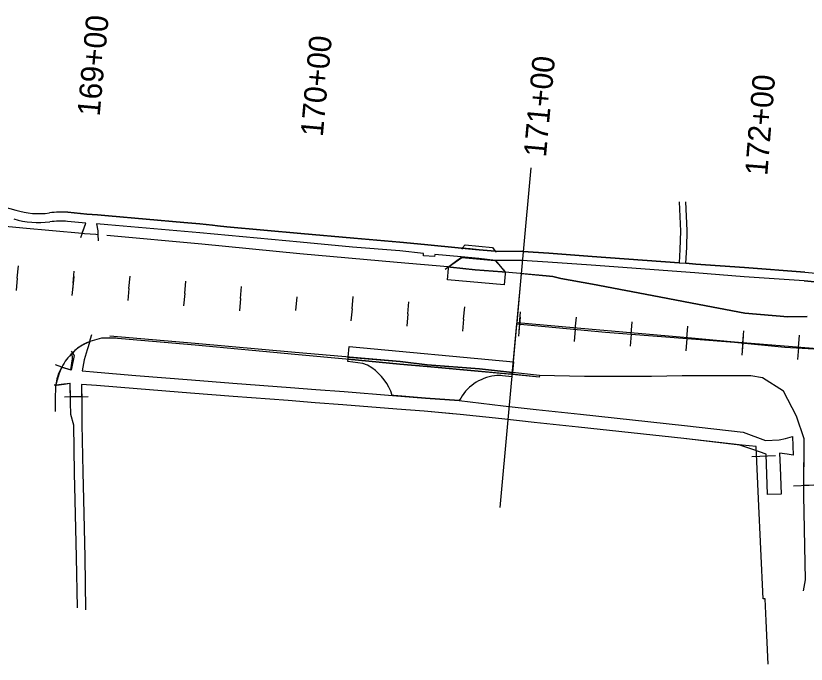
# Model space of a CAD drawing. Extents: x 20499880 to 20505309, y 7953507 to 7955507.
# Drawn here: x 20500587 to 20500939.7, y 7953820.8 to 7954110 of the extents above; entities that cross this region are included whole.
import ezdxf

# ---------------------------------------------------------------- set-up
doc = ezdxf.new("R2010")
doc.units = 0
for name, color, linetype in [('Alignment', 7, 'Continuous'), ('Curb', 7, 'Continuous'), ('Draft_0', 7, 'Continuous'), ('Entrance', 7, 'Continuous')]:
    doc.layers.add(name, color=color, linetype=linetype)

msp = doc.modelspace()

# ---------------------------------------------------------------- linework, layer by layer
at = {"layer": 'Alignment'}
for p, q in [((20500612.57, 7953990.69), (20500613.07, 7953996.12)), ((20500612.57, 7953990.69), (20500612.07, 7953985.25)), ((20500712.43, 7953984.62), (20500711.88, 7953978.53)), ((20500712.43, 7953984.62), (20500711.88, 7953978.53)), ((20500811.74, 7953972.46), (20500812.24, 7953977.9)), ((20500811.74, 7953972.46), (20500811.24, 7953967.02)), ((20500911.39, 7953964.08), (20500911.82, 7953969.52)), ((20500911.39, 7953964.08), (20500910.95, 7953958.64))]:
    msp.add_line(p, q, dxfattribs=at)
at = {"layer": 'Curb'}
for p, q in [((20500803.12, 7953890.74), (20500816.98, 7954042.24)), ((20500882.98, 7954026.94), (20500883.66, 7954013.96)), ((20500618.64, 7954021.56), (20500610.26, 7954022.39)), ((20500623.52, 7954021.15), (20500618.64, 7954021.56)), ((20500628.3, 7954020.71), (20500623.52, 7954021.15)), ((20500661.93, 7954017.8), (20500628.3, 7954020.71)), ((20500618.21, 7954017.54), (20500610.14, 7954018.27)), ((20500616.63, 7954013), (20500618.21, 7954017.54)), ((20500669.12, 7954017.16), (20500661.93, 7954017.8)), ((20500674.72, 7954016.63), (20500669.12, 7954017.16)), ((20500676.97, 7954016.28), (20500674.72, 7954016.63)), ((20500681.19, 7954015.83), (20500676.97, 7954016.28)), ((20500714.26, 7954012.88), (20500681.19, 7954015.83)), ((20500883.66, 7954013.96), (20500883.25, 7954005.81)), ((20500616.63, 7954013), (20500615.93, 7954010.98)), ((20500623.66, 7954012.45), (20500623.75, 7954009.64)), ((20500737.77, 7954010.78), (20500714.26, 7954012.88)), ((20500758.39, 7954009.06), (20500737.77, 7954010.78)), ((20500769.44, 7954007.93), (20500758.39, 7954009.06)), ((20500785.84, 7954006.38), (20500769.44, 7954007.93)), ((20500786.23, 7954006.36), (20500785.81, 7954005.88)), ((20500793.77, 7954005.61), (20500785.84, 7954006.38)), ((20500800.95, 7954005.06), (20500793.77, 7954005.61)), ((20500800.83, 7954005.1), (20500801.21, 7954004.6)), ((20500813.25, 7954004.92), (20500800.95, 7954005.06)), ((20500824.79, 7954004.16), (20500813.25, 7954004.92)), ((20500844.22, 7954002.69), (20500824.79, 7954004.16)), ((20500883.25, 7954005.81), (20500883, 7953999.85)), ((20500883, 7953999.85), (20500844.22, 7954002.69)), ((20500883, 7953999.85), (20500886, 7953999.67)), ((20500619.91, 7953964.38), (20500620.92, 7953967.89)), ((20500619.99, 7953964.72), (20500618.87, 7953964.16)), ((20500625.3, 7953966.21), (20500619.99, 7953964.72)), ((20500631.72, 7953966.19), (20500625.3, 7953966.21)), ((20500613.39, 7953960.67), (20500612.32, 7953959.54)), ((20500612.4, 7953959.57), (20500611.89, 7953960.45)), ((20500607.54, 7953953.34), (20500604.71, 7953954.25)), ((20500607.6, 7953953.31), (20500607.05, 7953952.29)), ((20500605.14, 7953946.48), (20500604.75, 7953945.1)), ((20500605.14, 7953945.29), (20500604.09, 7953945.17)), ((20500604.66, 7953944.09), (20500604.53, 7953939.56)), ((20500604.75, 7953945.1), (20500604.66, 7953944.09)), ((20500604.53, 7953939.56), (20500604.59, 7953936.8)), ((20500608.77, 7953940.02), (20500619.37, 7953940.18)), ((20500604.59, 7953936.8), (20500604.51, 7953933.47)), ((20500925.96, 7953913.79), (20500915.36, 7953913.31)), ((20500968.09, 7953901.45), (20500933.95, 7953900.26))]:
    msp.add_line(p, q, dxfattribs=at)
for points in [[(20500939.01, 7953995.67), (20500912.15, 7953997.69), (20500890.43, 7953999.26), (20500886, 7953999.67), (20500886.47, 7954006.61), (20500886.57, 7954014.16), (20500886, 7954027.04)], [(20500623.83, 7954012.28), (20500622.74, 7954012.45), (20500617.71, 7954012.79), (20500616.66, 7954012.91), (20500590.17, 7954015.26), (20500569.77, 7954017.17), (20500568.64, 7954017.31), (20500556.84, 7954018.48), (20500544.21, 7954019.57), (20500543.25, 7954019.65), (20500536.01, 7954020.3)], [(20500938.72, 7953991.76), (20500912.01, 7953993.62), (20500890.05, 7953995.34), (20500843.71, 7953998.77), (20500824.47, 7954000.17), (20500812.86, 7954000.88), (20500801, 7954000.89), (20500793.63, 7954001.68), (20500785.78, 7954002.49), (20500773.95, 7954003.53), (20500773.84, 7954002.6), (20500768.96, 7954002.99), (20500768.97, 7954004.02), (20500758.33, 7954005.1), (20500737.31, 7954006.8), (20500713.83, 7954008.95), (20500669.14, 7954013.13), (20500628.01, 7954016.82), (20500623.05, 7954017.22), (20500623.61, 7954014.09), (20500623.66, 7954012.45)], [(20500823.72, 7953994.07), (20500805.33, 7953995.61), (20500804.02, 7953995.75), (20500791.97, 7953996.74), (20500780.96, 7953997.91), (20500779.85, 7953997.99), (20500757.17, 7953999.99), (20500713.73, 7954003.89), (20500670.06, 7954008.07), (20500627.62, 7954011.95)], [(20500786.07, 7954002.28), (20500778.58, 7953996.88)], [(20500800.92, 7954000.94), (20500805.52, 7953995.49)], [(20500940.08, 7953975.84), (20500931.44, 7953975.72), (20500912.3, 7953977.34), (20500888.79, 7953981.79), (20500874.13, 7953984.67), (20500844.31, 7953990.29), (20500830.14, 7953992.87), (20500826.56, 7953993.71), (20500823.72, 7953994.07)], [(20500939.01, 7953995.67), (20500943.94, 7953995.2)], [(20500938.72, 7953991.76), (20500943.48, 7953991.35)], [(20500820.58, 7953948.84), (20500808.35, 7953950.07), (20500807.31, 7953950.11), (20500793.37, 7953951.41), (20500770.62, 7953953.52), (20500758.43, 7953954.62), (20500736.93, 7953956.6), (20500735.9, 7953956.75), (20500711.5, 7953958.93), (20500667.11, 7953963.07), (20500628.95, 7953966.3)], [(20500820.68, 7953949.54), (20500793.87, 7953952.59), (20500770.59, 7953954.37), (20500758.5, 7953955.73), (20500711.67, 7953959.77), (20500667.07, 7953963.82), (20500629, 7953967.1)], [(20500612.4, 7953959.57), (20500613.02, 7953958.49), (20500611.73, 7953951.98), (20500607.54, 7953953.34)], [(20500938.41, 7953853.48), (20500939.42, 7953858.42), (20500938.56, 7953896.04), (20500938.84, 7953921.37), (20500935.31, 7953931.34), (20500929.6, 7953942.5), (20500920.16, 7953948.44), (20500914.94, 7953949.34), (20500897.08, 7953949.45), (20500884.36, 7953949.42), (20500870.63, 7953949.1), (20500840.7, 7953949.08), (20500820.68, 7953949.54)], [(20500605.14, 7953945.29), (20500608.58, 7953945.66), (20500611.14, 7953946.06), (20500611.27, 7953937.42), (20500611.45, 7953932.33), (20500612.72, 7953927.54), (20500613.02, 7953906.04), (20500613.35, 7953893.93), (20500613.95, 7953868.59), (20500614.43, 7953845.85)], [(20500922.7, 7953820.79), (20500921.82, 7953840.18), (20500921.44, 7953849.94), (20500920.45, 7953849.95), (20500918.39, 7953894.61), (20500917.35, 7953917.84), (20500911.04, 7953918.52), (20500885.09, 7953921.38), (20500838.13, 7953926.44), (20500818.24, 7953928.58), (20500803.83, 7953930.2), (20500785.26, 7953932.19), (20500781.85, 7953932.48), (20500769.24, 7953933.59), (20500757.04, 7953934.51), (20500732.86, 7953936.48), (20500720.62, 7953937.31), (20500708.53, 7953938.34), (20500684.02, 7953940.23), (20500664.91, 7953941.68), (20500641.23, 7953943.53), (20500623.08, 7953945.07), (20500616.29, 7953945.48), (20500616.4, 7953937.44), (20500616.48, 7953927.77), (20500616.95, 7953906.44), (20500617.27, 7953894.22), (20500617.86, 7953868.5), (20500618.17, 7953845.1)]]:
    msp.add_lwpolyline(points, dxfattribs=at)
for centre, major_axis, ratio, start_param, end_param in [((20500597.28, 7954056.96), (35.13, -2.99), 0.998255, 4.501703, 4.932072), ((20500607.5, 7953981.35), (-40.22, -10.21), 0.990335, 4.399703, 4.598832), ((20500597.14, 7954056.56), (38.51, -5.08), 0.998991, 4.555055, 4.97441), ((20500606.72, 7953983.52), (-36.03, -4.19), 0.961012, 4.506466, 4.725676), ((20500627.32, 7953944.72), (-16.37, -13.69), 0.992656, 4.428112, 4.733636), ((20500624.32, 7953945.55), (-16.13, -8.94), 0.999405, 4.915161, 5.342028), ((20500632.73, 7953940.59), (-10.97, -33.6), 0.796506, 4.623076, 4.796293)]:
    msp.add_ellipse(centre, major_axis=major_axis, ratio=ratio, start_param=start_param, end_param=end_param, dxfattribs=at)
at = {"layer": 'Draft_0'}
for p, q in [((20500579.82, 7954025.19), (20500587.01, 7954023.29)), ((20500606.31, 7953950.89), (20500607.6, 7953953.31))]:
    msp.add_line(p, q, dxfattribs=at)
for points in [[(20500610.26, 7954022.39), (20500618.64, 7954021.56), (20500623.52, 7954021.15), (20500628.3, 7954020.71), (20500661.93, 7954017.8), (20500669.12, 7954017.16), (20500674.72, 7954016.63), (20500676.97, 7954016.28), (20500681.19, 7954015.83), (20500714.26, 7954012.88), (20500737.77, 7954010.78), (20500758.39, 7954009.06), (20500769.44, 7954007.93), (20500785.84, 7954006.38), (20500793.77, 7954005.61), (20500800.95, 7954005.06), (20500813.25, 7954004.92), (20500824.79, 7954004.16), (20500844.22, 7954002.69), (20500883, 7953999.85), (20500886, 7953999.67), (20500890.43, 7953999.26), (20500912.15, 7953997.69), (20500939.01, 7953995.67), (20500943.94, 7953995.2)], [(20500943.48, 7953991.35), (20500938.72, 7953991.76), (20500912.01, 7953993.62), (20500890.05, 7953995.34), (20500843.71, 7953998.77), (20500824.47, 7954000.17), (20500812.86, 7954000.88), (20500801, 7954000.89), (20500793.63, 7954001.68), (20500785.78, 7954002.49), (20500773.95, 7954003.53), (20500773.84, 7954002.6), (20500768.96, 7954002.99), (20500768.97, 7954004.02), (20500758.33, 7954005.1), (20500737.31, 7954006.8), (20500713.83, 7954008.95), (20500669.14, 7954013.13), (20500628.01, 7954016.82), (20500623.05, 7954017.22), (20500623.61, 7954014.09), (20500623.66, 7954012.3), (20500622.74, 7954012.45), (20500617.71, 7954012.79), (20500616.66, 7954012.91), (20500616.6, 7954012.92), (20500618.21, 7954017.54), (20500610.14, 7954018.27)], [(20500959.52, 7953960.25), (20500907.68, 7953964.37), (20500888.47, 7953966.18), (20500842.55, 7953970.29), (20500810.65, 7953973.03), (20500812.66, 7953995), (20500823.72, 7953994.07), (20500826.56, 7953993.71), (20500830.14, 7953992.87), (20500844.31, 7953990.29), (20500874.13, 7953984.67), (20500888.79, 7953981.79), (20500912.3, 7953977.34), (20500931.44, 7953975.72), (20500940.08, 7953975.84)], [(20500960.87, 7953901.2), (20500938.61, 7953900.42), (20500938.84, 7953921.37), (20500935.31, 7953931.34), (20500929.6, 7953942.5), (20500920.16, 7953948.44), (20500914.94, 7953949.34), (20500897.08, 7953949.45), (20500884.36, 7953949.42), (20500870.63, 7953949.1), (20500840.7, 7953949.08), (20500820.68, 7953949.54), (20500820.58, 7953948.84), (20500808.55, 7953950.05), (20500810.61, 7953972.56), (20500850.16, 7953968.94), (20500907.68, 7953964.37), (20500930.1, 7953962.26), (20500948.33, 7953961.08)], [(20500619.07, 7953964.21), (20500619.99, 7953964.72), (20500620.01, 7953964.73), (20500618.8, 7953961.07), (20500617.48, 7953956.6), (20500616.59, 7953951.67), (20500623.35, 7953951.01), (20500640.56, 7953949.52), (20500665.39, 7953947.59), (20500683.88, 7953946.15), (20500709.61, 7953944.25), (20500720.95, 7953943.31), (20500733.55, 7953942.37), (20500755.16, 7953940.63), (20500769.77, 7953939.45), (20500784.83, 7953938.37), (20500804.43, 7953936.03), (20500819.24, 7953934.41), (20500838.99, 7953932.25), (20500885.38, 7953927.28), (20500911.54, 7953924.34), (20500921.59, 7953920.53), (20500927.64, 7953920.89), (20500930.41, 7953921.45), (20500933.54, 7953922.33), (20500933.89, 7953913.98), (20500931.22, 7953914.4), (20500927.8, 7953914.87), (20500928.14, 7953908.66), (20500928.56, 7953896.65), (20500922.42, 7953896.4), (20500921.85, 7953914.48), (20500915.89, 7953916.51), (20500910.01, 7953918.51), (20500885.09, 7953921.38), (20500838.13, 7953926.44), (20500818.24, 7953928.58), (20500803.83, 7953930.2), (20500785.26, 7953932.19), (20500769.24, 7953933.59), (20500757.04, 7953934.51), (20500732.86, 7953936.48), (20500720.62, 7953937.31), (20500708.53, 7953938.34), (20500684.02, 7953940.23), (20500664.91, 7953941.68), (20500641.23, 7953943.53), (20500623.08, 7953945.07), (20500616.29, 7953945.48), (20500616.36, 7953940.13), (20500611.37, 7953940.06), (20500611.24, 7953945.96), (20500608.45, 7953945.67), (20500605, 7953945.31), (20500605.45, 7953948.04)], [(20500607.6, 7953953.31), (20500611.63, 7953952.03), (20500612.35, 7953957), (20500612.12, 7953959.57), (20500613.28, 7953960.68)], [(20500745.93, 7953953.01), (20500744, 7953954.09), (20500741.79, 7953954.85), (20500735.2, 7953955.82), (20500735.3, 7953956.81), (20500758.43, 7953954.62), (20500770.62, 7953953.52), (20500793.37, 7953951.41), (20500808.36, 7953950.07), (20500808.29, 7953948.93), (20500804.18, 7953949.42), (20500803.4, 7953949.49), (20500802.59, 7953949.52), (20500801.7, 7953949.5), (20500800.65, 7953949.42)], [(20500784.88, 7953938.38), (20500769.77, 7953939.45), (20500755.73, 7953940.58), (20500754.96, 7953940.69)]]:
    msp.add_lwpolyline(points, dxfattribs=at)
for points in [[(20500799.66, 7954006.65), (20500800.86, 7954005.06), (20500797.36, 7954005.34), (20500797.36, 7954005.34), (20500797.36, 7954005.34), (20500793.77, 7954005.61), (20500789.81, 7954006), (20500786.22, 7954006.34), (20500787.46, 7954007.77)], [(20500800.75, 7954000.91), (20500800.95, 7954000.89), (20500804.55, 7953996.64), (20500805.42, 7953995.6), (20500804.02, 7953995.75), (20500791.97, 7953996.74), (20500780.96, 7953997.91), (20500780.09, 7953997.97), (20500786.03, 7954002.25)], [(20500779.58, 7953992.26), (20500780.02, 7953997.3), (20500780.08, 7953997.96), (20500780.09, 7953997.97), (20500780.96, 7953997.91), (20500791.97, 7953996.74), (20500804.02, 7953995.75), (20500805.42, 7953995.6), (20500805.36, 7953994.94), (20500804.92, 7953990.06)], [(20500808.63, 7953950.91), (20500793.87, 7953952.59), (20500770.59, 7953954.37), (20500758.5, 7953955.73), (20500735.36, 7953957.73), (20500735.77, 7953962.48), (20500809.06, 7953955.68)], [(20500735.38, 7953957.72), (20500758.5, 7953955.73), (20500770.59, 7953954.37), (20500793.87, 7953952.59), (20500808.63, 7953950.91), (20500808.55, 7953950.05), (20500793.37, 7953951.41), (20500770.62, 7953953.52), (20500758.43, 7953954.62), (20500735.3, 7953956.81)]]:
    msp.add_lwpolyline(points, close=True, dxfattribs=at)
for centre, radius, start, end in [((20500731.25, 7953932.78), 25, 18.4488, 54.0324), ((20500803.3, 7953928.85), 20.73, 97.322, 152.6444)]:
    msp.add_arc(centre, radius, start, end, dxfattribs=at)
for centre, major_axis, ratio, start_param, end_param in [((20500597.28, 7954056.96), (35.13, -2.99), 0.998255, 4.501703, 4.932072), ((20500607.5, 7953981.35), (-40.22, -10.21), 0.990335, 4.399703, 4.598832), ((20500597.14, 7954056.56), (38.51, -5.08), 0.998991, 4.555055, 4.97441), ((20500606.72, 7953983.52), (-36.03, -4.19), 0.961012, 4.506466, 4.725676), ((20500629.34, 7953946.11), (-23.21, -0.04), 0.87012, 5.169515, 5.475038), ((20500603.89, 7953951.73), (4.77, 16.64), 0.147804, 4.531233, 4.704449), ((20500624.32, 7953945.55), (-16.13, -8.94), 0.999405, 5.341793, 5.342028)]:
    msp.add_ellipse(centre, major_axis=major_axis, ratio=ratio, start_param=start_param, end_param=end_param, dxfattribs=at)
at = {"layer": 'Entrance'}
for p, q in [((20500587.68, 7953992.96), (20500588.17, 7953998.4)), ((20500587.68, 7953992.96), (20500587.18, 7953987.53)), ((20500612.85, 7953993.73), (20500612.29, 7953987.64)), ((20500612.85, 7953993.73), (20500612.29, 7953987.64)), ((20500637.47, 7953988.41), (20500637.97, 7953993.85)), ((20500662.36, 7953986.13), (20500662.86, 7953991.57)), ((20500687.26, 7953983.85), (20500687.76, 7953989.29)), ((20500637.47, 7953988.41), (20500636.97, 7953982.97)), ((20500662.36, 7953986.13), (20500661.87, 7953980.69)), ((20500687.26, 7953983.85), (20500686.76, 7953978.41)), ((20500712.43, 7953984.62), (20500711.88, 7953978.53)), ((20500712.43, 7953984.62), (20500711.88, 7953978.53)), ((20500737.05, 7953979.29), (20500737.55, 7953984.73)), ((20500761.95, 7953977.02), (20500762.44, 7953982.45)), ((20500737.05, 7953979.29), (20500736.55, 7953973.86)), ((20500786.84, 7953974.74), (20500787.34, 7953980.18)), ((20500761.95, 7953977.02), (20500761.45, 7953971.58)), ((20500786.84, 7953974.74), (20500786.35, 7953969.3)), ((20500812.02, 7953975.51), (20500811.46, 7953969.41)), ((20500812.02, 7953975.51), (20500811.46, 7953969.41)), ((20500836.64, 7953970.18), (20500837.13, 7953975.62)), ((20500861.54, 7953968.04), (20500861.98, 7953973.48)), ((20500886.46, 7953966.06), (20500886.9, 7953971.5)), ((20500836.64, 7953970.18), (20500836.14, 7953964.74)), ((20500861.54, 7953968.04), (20500861.11, 7953962.6)), ((20500936.31, 7953962.1), (20500936.74, 7953967.54)), ((20500886.46, 7953966.06), (20500886.03, 7953960.62)), ((20500911.63, 7953967.13), (20500911.14, 7953961.03)), ((20500911.63, 7953967.13), (20500911.14, 7953961.03)), ((20500936.31, 7953962.1), (20500935.87, 7953956.66))]:
    msp.add_line(p, q, dxfattribs=at)

# ---------------------------------------------------------------- texts
at = {"layer": 'Alignment'}
msp.add_text('170+00', height=10.02, rotation=84.7714, dxfattribs=at).set_placement((20500723.98, 7954055.8))
at = {"layer": 'Entrance'}
for s, rotation, p in [('169+00', 84.7714, (20500624.4, 7954064.92)), ('170+00', 84.7714, (20500723.98, 7954055.8)), ('171+00', 84.7714, (20500823.56, 7954046.69)), ('172+00', 85.4564, (20500922.32, 7954038.45))]:
    msp.add_text(s, height=10.02, rotation=rotation, dxfattribs=at).set_placement(p)

doc.saveas('drawing.dxf')
